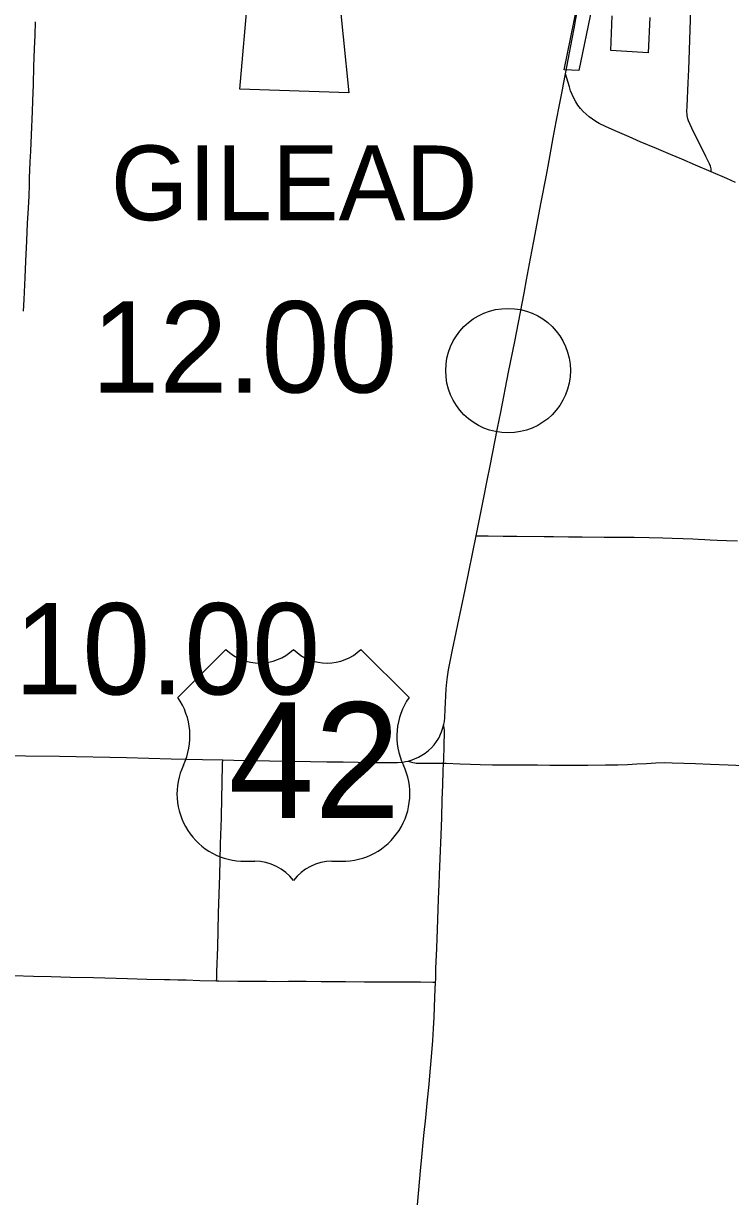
# Model space of a CAD drawing. Extents: x 9078 to 9739, y 4248 to 4966.
# Drawn here: x 9349.9 to 9392.4, y 4556.7 to 4627.8 of the extents above; entities that cross this region are included whole.
import ezdxf

# ---------------------------------------------------------------- set-up
doc = ezdxf.new("R2010")
doc.units = 0
for name, color, linetype in [('Default', 7, 'Continuous'), ('GM_X_Corporation', 7, 'Continuous'), ('GM_X_County_Road', 7, 'Continuous'), ('GM_X_State_Route', 7, 'Continuous'), ('GM_X_Township_Road', 7, 'Continuous'), ('GM_X_Township_Text', 7, 'Continuous'), ('GM_X_US_Route', 7, 'Continuous'), ('GM_X_US_Shield', 7, 'Continuous')]:
    doc.layers.add(name, color=color, linetype=linetype)

msp = doc.modelspace()

# ---------------------------------------------------------------- linework, layer by layer
at = {"layer": 'Default'}
msp.add_circle((9379.043, 4606.897), 3.75, dxfattribs=at)
at = {"layer": 'GM_X_Corporation'}
for points in [[(9368.784, 4630.379), (9369.459, 4623.616), (9362.907, 4623.847), (9363.407, 4629.598)], [(9384.079, 4628.751), (9383.299, 4624.966), (9382.414, 4625), (9383.423, 4629.946)], [(9387.584, 4628.152), (9387.467, 4626.039), (9385.224, 4626.166), (9385.304, 4628.261)]]:
    msp.add_lwpolyline(points, dxfattribs=at)
at = {"layer": 'GM_X_County_Road'}
for points in [[(9391.271, 4618.866), (9391.272, 4618.953), (9391.265, 4619.044), (9391.253, 4619.12), (9391.227, 4619.2), (9391.162, 4619.352), (9390.951, 4619.781), (9390.616, 4620.459), (9390.212, 4621.269), (9389.999, 4621.712), (9389.906, 4621.938), (9389.862, 4622.061), (9389.84, 4622.152), (9389.824, 4622.252), (9389.814, 4622.331), (9389.809, 4622.493), (9389.825, 4622.82), (9389.887, 4624.217), (9389.919, 4625.038), (9389.962, 4626.189), (9390.052, 4628.653), (9390.078, 4629.584)], [(9375.162, 4583.256), (9375.169, 4583.433), (9375.2, 4584.335), (9375.226, 4585.148), (9375.22, 4585.243), (9375.204, 4585.364), (9375.177, 4585.499), (9375.166, 4585.557)], [(9374.68, 4570.069), (9374.688, 4570.24), (9374.707, 4570.895), (9374.754, 4572.122), (9374.795, 4573.27), (9374.823, 4573.843), (9374.863, 4575.072), (9374.897, 4575.974), (9374.924, 4576.547), (9374.958, 4577.531), (9375.013, 4578.924), (9375.05, 4579.99), (9375.086, 4581.056), (9375.115, 4581.958), (9375.143, 4582.778), (9375.162, 4583.256)], [(9349.26, 4570.469), (9350.49, 4570.441), (9351.556, 4570.412), (9352.704, 4570.385), (9354.098, 4570.349), (9356.148, 4570.3), (9357.296, 4570.266), (9358.362, 4570.241), (9358.688, 4570.232), (9359.179, 4570.222), (9359.671, 4570.207), (9360.49, 4570.178), (9361.506, 4570.162)], [(9361.506, 4570.162), (9361.639, 4570.16), (9362.787, 4570.145), (9363.771, 4570.138), (9364.509, 4570.128), (9364.919, 4570.126), (9365.821, 4570.131), (9366.887, 4570.129), (9367.79, 4570.123), (9369.266, 4570.109), (9370.414, 4570.105), (9371.727, 4570.095), (9372.793, 4570.087), (9373.776, 4570.087), (9374.513, 4570.073), (9374.68, 4570.069)], [(9373.597, 4556.674), (9373.678, 4557.572), (9373.783, 4558.716), (9373.864, 4559.533), (9373.944, 4560.431), (9373.979, 4560.84), (9374.086, 4561.901), (9374.17, 4562.799), (9374.288, 4563.941), (9374.355, 4564.676), (9374.434, 4565.575), (9374.513, 4566.556), (9374.558, 4567.293), (9374.592, 4567.948), (9374.643, 4569.176), (9374.68, 4570.069)]]:
    msp.add_lwpolyline(points, dxfattribs=at)
at = {"layer": 'GM_X_State_Route'}
msp.add_lwpolyline([(9392.728, 4618.225), (9392.205, 4618.464), (9391.271, 4618.866), (9390.322, 4619.274), (9389.492, 4619.627), (9388.815, 4619.92), (9387.985, 4620.27), (9387.001, 4620.681), (9386.326, 4620.977), (9385.498, 4621.332), (9384.9, 4621.599), (9384.533, 4621.777), (9384.32, 4621.897), (9384.116, 4622.029), (9383.921, 4622.176), (9383.735, 4622.334), (9383.561, 4622.505), (9383.399, 4622.688), (9383.25, 4622.882), (9383.115, 4623.085), (9382.996, 4623.298), (9382.894, 4623.52), (9382.808, 4623.748), (9382.737, 4623.983), (9382.668, 4624.237), (9382.495, 4624.773)], dxfattribs=at)
at = {"layer": 'GM_X_Township_Road'}
for points in [[(9349.89, 4610.478), (9349.922, 4611.188), (9349.975, 4612.5), (9350.018, 4613.483), (9350.075, 4614.712), (9350.127, 4615.777), (9350.181, 4616.678), (9350.215, 4617.415), (9350.236, 4618.07), (9350.249, 4618.48), (9350.294, 4619.463), (9350.324, 4620.118), (9350.359, 4621.102), (9350.421, 4622.495), (9350.449, 4623.151), (9350.475, 4624.135), (9350.508, 4625.2), (9350.546, 4626.266), (9350.576, 4627.086), (9350.598, 4627.906)], [(9377.123, 4596.942), (9377.356, 4596.943), (9377.849, 4596.947), (9378.751, 4596.935), (9379.571, 4596.933), (9381.212, 4596.919), (9381.787, 4596.911), (9382.689, 4596.898), (9383.509, 4596.884), (9384.822, 4596.873), (9386.627, 4596.864), (9387.53, 4596.857), (9388.351, 4596.838), (9388.924, 4596.819), (9389.581, 4596.797), (9390.155, 4596.768), (9390.481, 4596.749), (9390.889, 4596.724), (9391.216, 4596.702), (9391.625, 4596.68), (9392.198, 4596.66), (9392.854, 4596.65)], [(9361.506, 4570.162), (9361.51, 4570.294), (9361.525, 4570.704), (9361.569, 4572.18), (9361.591, 4573.164), (9361.622, 4574.231), (9361.661, 4575.378), (9361.693, 4576.527), (9361.717, 4577.429), (9361.747, 4578.413), (9361.79, 4579.971), (9361.818, 4581.201), (9361.842, 4582.021), (9361.865, 4583.252), (9361.869, 4583.46)], [(9373.028, 4583.389), (9373.121, 4583.354), (9373.223, 4583.315), (9373.316, 4583.293), (9373.428, 4583.276), (9373.511, 4583.269), (9373.758, 4583.259), (9374.333, 4583.256), (9375.162, 4583.256)], [(9375.162, 4583.256), (9375.317, 4583.256), (9376.135, 4583.218), (9376.792, 4583.198), (9377.366, 4583.183), (9378.103, 4583.17), (9378.595, 4583.164), (9379.17, 4583.161), (9379.991, 4583.154), (9380.811, 4583.153), (9381.549, 4583.148), (9382.616, 4583.145), (9383.847, 4583.146), (9384.914, 4583.156), (9385.653, 4583.17), (9386.227, 4583.183), (9386.801, 4583.212), (9387.373, 4583.251), (9387.946, 4583.285), (9388.437, 4583.298), (9388.929, 4583.291), (9390.323, 4583.241), (9391.225, 4583.205), (9392.291, 4583.163), (9393.685, 4583.111)]]:
    msp.add_lwpolyline(points, dxfattribs=at)
at = {"layer": 'GM_X_US_Route'}
for points in [[(9382.495, 4624.773), (9382.898, 4626.873), (9383.033, 4627.597), (9383.121, 4628.079), (9383.214, 4628.56), (9383.471, 4629.953)], [(9374.982, 4585.009), (9375.036, 4585.142), (9375.138, 4585.453), (9375.166, 4585.557), (9375.18, 4585.61), (9375.211, 4585.769), (9375.239, 4586.012), (9375.268, 4586.502), (9375.324, 4587.732), (9375.354, 4588.142), (9375.393, 4588.469), (9375.46, 4588.875), (9375.703, 4590.081), (9375.918, 4591.126), (9376.02, 4591.607), (9376.237, 4592.651), (9376.454, 4593.695), (9377.123, 4596.942), (9377.249, 4597.552), (9377.567, 4599.162), (9377.793, 4600.287), (9377.964, 4601.174), (9378.41, 4603.427), (9378.6, 4604.393), (9379.076, 4606.808), (9379.446, 4608.658), (9380.007, 4611.558), (9380.157, 4612.364), (9380.4, 4613.653), (9380.596, 4614.701), (9381.042, 4617.038), (9381.329, 4618.57), (9381.45, 4619.215), (9381.765, 4620.907), (9381.949, 4621.874), (9382.161, 4623.002), (9382.314, 4623.809), (9382.38, 4624.142), (9382.495, 4624.773)], [(9348.854, 4583.728), (9350.003, 4583.713), (9352.053, 4583.674), (9356.072, 4583.594), (9358.779, 4583.531), (9360.665, 4583.486), (9361.869, 4583.46), (9363.208, 4583.432), (9364.685, 4583.403), (9365.751, 4583.392), (9367.145, 4583.367), (9368.13, 4583.349), (9369.114, 4583.335), (9370.918, 4583.305), (9371.984, 4583.293), (9372.393, 4583.304), (9372.718, 4583.33), (9372.878, 4583.355), (9373.028, 4583.389), (9373.271, 4583.461), (9373.423, 4583.518), (9373.645, 4583.619), (9373.858, 4583.738), (9374.063, 4583.872), (9374.254, 4584.022), (9374.432, 4584.189), (9374.595, 4584.37), (9374.74, 4584.566), (9374.871, 4584.772), (9374.945, 4584.916), (9374.982, 4585.009)]]:
    msp.add_lwpolyline(points, dxfattribs=at)
at = {"layer": 'GM_X_US_Shield'}
for p, q in [((9362.066, 4590.115), (9359.166, 4587.215)), ((9373.088, 4587.215), (9370.187, 4590.115)), ((9363.226, 4577.354), (9363.806, 4577.354)), ((9368.447, 4577.354), (9369.027, 4577.354))]:
    msp.add_line(p, q, dxfattribs=at)
for centre, radius, start, end in [((9364.096, 4592.187), 2.9, 225.573, 314.427), ((9368.157, 4592.187), 2.9, 225.573, 314.427), ((9355.84, 4584.886), 4.061, 334.54712, 35.00093), ((9376.414, 4584.886), 4.061, 144.99907, 205.45288), ((9363.181, 4581.414), 4.061, 154.83192, 270.63826), ((9369.072, 4581.414), 4.061, 269.36174, 25.16808), ((9363.806, 4574.453), 2.9, 36.8699, 90), ((9368.447, 4574.453), 2.9, 90, 143.1301)]:
    msp.add_arc(centre, radius, start, end, dxfattribs=at)

# ---------------------------------------------------------------- texts
at = {"layer": 'Default'}
for s, p in [('12.00', (9353.974, 4605.578)), ('10.00', (9349.332, 4587.398))]:
    msp.add_text(s, height=5.5, dxfattribs=at).set_placement(p)
at = {"layer": 'GM_X_Township_Text'}
msp.add_text('GILEAD', height=4.5, rotation=0.00001, dxfattribs=at).set_placement((9355.137, 4615.954))
at = {"layer": 'GM_X_US_Shield'}
msp.add_text('42', height=6.961, dxfattribs=at).set_placement((9362.208, 4579.964))

doc.saveas('drawing.dxf')
